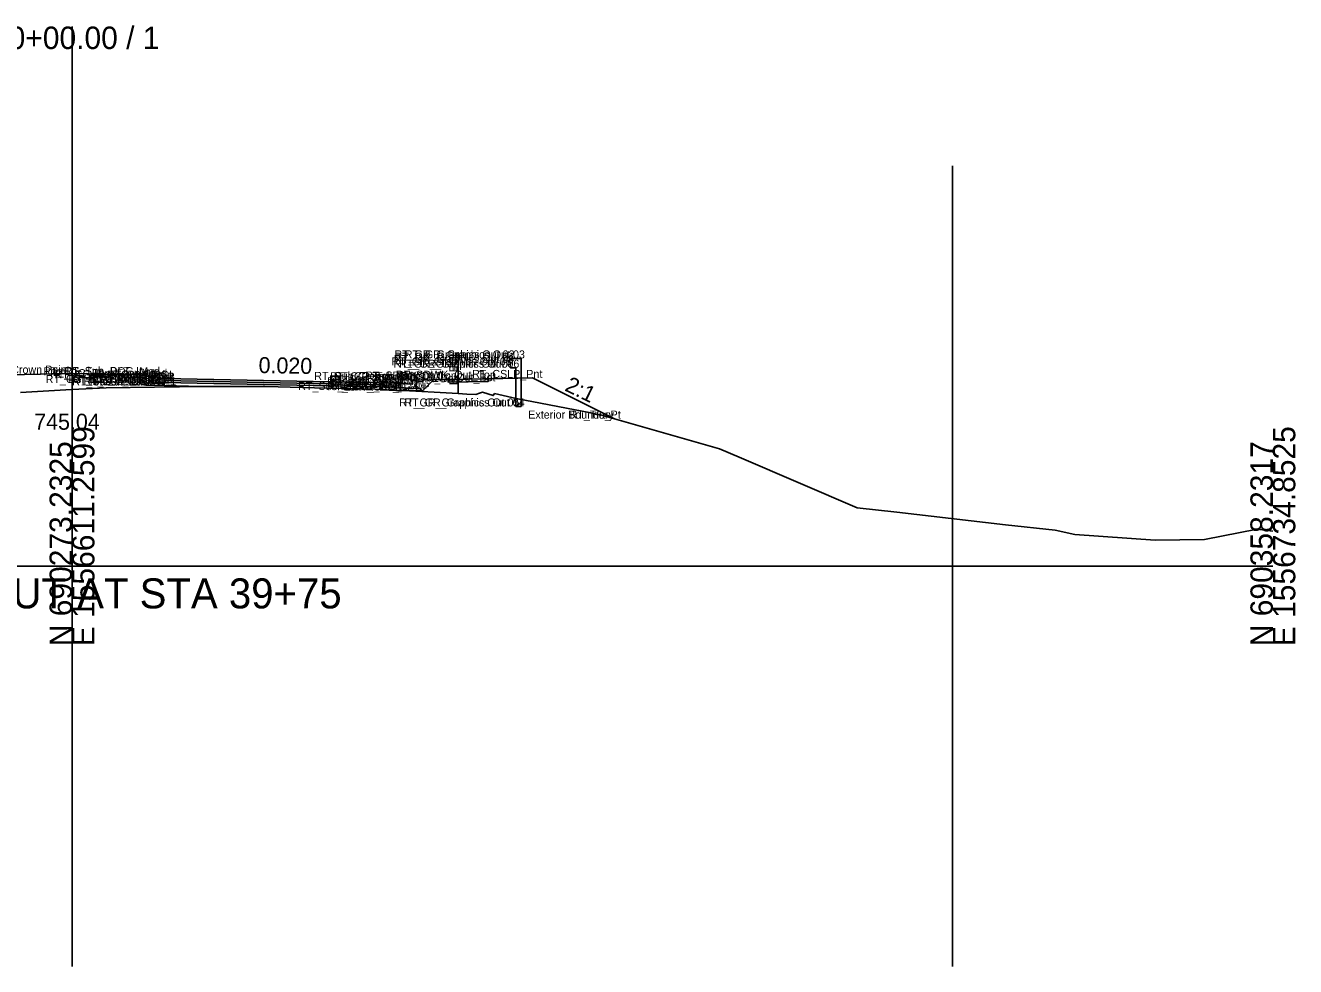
# Model space of a CAD drawing. Extents: x -26 to 6300, y -50 to 9577.
# Drawn here: x 144.2 to 302.8, y 6450 to 6567.5 of the extents above; entities that cross this region are included whole.
import ezdxf

# ---------------------------------------------------------------- set-up
doc = ezdxf.new("R2010")
doc.units = 0
for name, color, linetype in [('Default', 7, 'Continuous'), ('Exist CMT Pavement', 7, 'Continuous'), ('Exist Cross Section Cell', 7, 'Continuous'), ('Exist XS Center Line Elevation Label', 7, 'Continuous'), ('Exist XS Ground Line', 7, 'Continuous'), ('Prop CMT Conc Surface', 7, 'Continuous'), ('Prop CMT Concrete Structures', 7, 'Continuous'), ('Prop CMT Guardrail Graphics', 7, 'Continuous'), ('Prop CMT Pvmt Course 1', 7, 'Continuous'), ('Prop CMT Pvmt Course 1 CG', 7, 'Continuous'), ('Prop CMT Pvmt Course 2', 7, 'Continuous'), ('Prop CMT Pvmt Course 3', 7, 'Continuous'), ('Prop CMT Pvmt Surface', 7, 'Continuous'), ('Prop CMT Slope Grass', 7, 'Continuous'), ('Prop CMT Subgrade Earthwork', 7, 'Continuous'), ('Prop XS Earthwork Shape', 7, 'Continuous'), ('Prop XS Label Text', 7, 'Continuous'), ('Prop XS SE Text', 7, 'Continuous'), ('Prop XS Side Slope Text', 7, 'Continuous'), ('Prop XSC Text', 7, 'Continuous'), ('Scratch_Level_2', 7, 'Continuous'), ('Scratch_Level_9', 7, 'Continuous')]:
    doc.layers.add(name, color=color, linetype=linetype)

msp = doc.modelspace()

# ---------------------------------------------------------------- linework, layer by layer
at = {"layer": 'Exist CMT Pavement'}
msp.add_lwpolyline([(166.1, 6522.45), (168.19, 6522.46), (169.86, 6522.45), (171.3, 6522.45), (172.75, 6522.44), (174.06, 6522.42), (175.76, 6522.41), (178.77, 6522.32), (181.79, 6522.24), (184.82, 6522.17), (187.85, 6522.1), (188.5, 6522.07)], dxfattribs=at)
at = {"layer": 'Exist Cross Section Cell'}
for p, q in [((150, 6500), (150, 6567.38)), ((0, 6500), (150, 6500)), ((150, 6500), (300, 6500))]:
    msp.add_line(p, q, dxfattribs=at)
at = {"layer": 'Exist XS Ground Line'}
msp.add_lwpolyline([(143.57, 6521.71), (149.23, 6522.02), (150, 6522.06), (154.26, 6522.26), (160.3, 6522.36), (166.53, 6522.46), (169.86, 6522.45), (172.75, 6522.44), (174.06, 6522.42), (175.76, 6522.41), (181.79, 6522.24), (187.85, 6522.1), (190.04, 6521.99), (192.16, 6521.9), (195.23, 6521.74), (198.23, 6521.57), (199.3, 6521.5), (200.46, 6521.45), (200.9, 6521.6), (201.26, 6521.72), (202.62, 6521.31), (202.79, 6521.55), (205.5, 6520.96), (214.8, 6519.15), (215.56, 6518.95), (216.01, 6518.9), (230.88, 6514.66), (231.96, 6514.19), (233.64, 6513.5), (248.06, 6507.29), (253.04, 6506.73), (266.59, 6505.16), (272.79, 6504.52), (275.25, 6503.97), (285.31, 6503.24), (291.48, 6503.34), (298.02, 6504.64), (300, 6504.39)], dxfattribs=at)
at = {"layer": 'Prop CMT Conc Surface'}
for points in [[(161.5, 6523.42), (160.75, 6523.44), (160.75, 6523.6), (159.99, 6523.85)], [(190.5, 6522.84), (192.5, 6522.72)], [(192.5, 6522.72), (192.5, 6523.22), (193, 6523.22)], [(197, 6523.31), (202, 6523.41)]]:
    msp.add_lwpolyline(points, dxfattribs=at)
at = {"layer": 'Prop CMT Concrete Structures'}
for points in [[(161.5, 6523.42), (160.75, 6523.44), (160.75, 6523.6), (159.99, 6523.85)], [(159.99, 6523.85), (159.99, 6522.87)], [(159.99, 6522.87), (161.5, 6522.84)], [(161.5, 6522.84), (161.5, 6523.42)], [(190.5, 6522.84), (192.5, 6522.72), (192.5, 6523.22), (193, 6523.22)], [(193, 6523.22), (193, 6522.21), (190.5, 6522.26)], [(190.5, 6522.26), (190.5, 6522.84)], [(202, 6523.41), (197, 6523.31)], [(197, 6523.31), (197, 6522.98)], [(197, 6522.98), (202, 6523.08)], [(202, 6523.08), (202, 6523.41)]]:
    msp.add_lwpolyline(points, dxfattribs=at)
at = {"layer": 'Prop CMT Guardrail Graphics'}
for points in [[(206.1, 6525.95), (204.77, 6525.95), (204.5, 6525.66)], [(206.1, 6519.95), (206.1, 6525.95)], [(204.5, 6525.66), (204.77, 6525.37)], [(204.77, 6525.37), (204.5, 6525.08)], [(204.5, 6525.08), (204.77, 6524.79), (205.44, 6524.79)], [(205.44, 6524.79), (205.44, 6519.95)], [(205.44, 6519.95), (206.1, 6519.95)]]:
    msp.add_lwpolyline(points, dxfattribs=at)
at = {"layer": 'Prop CMT Pvmt Course 1'}
for points in [[(161.5, 6523.42), (190.5, 6522.84)], [(161.5, 6523.17), (161.5, 6523.42)], [(190.5, 6522.59), (161.5, 6523.17)], [(161.5, 6523.17), (161.5, 6523.17), (161.5, 6523.17)], [(188.5, 6522.88), (188.5, 6522.63)], [(190.5, 6522.84), (190.5, 6522.59)]]:
    msp.add_lwpolyline(points, dxfattribs=at)
at = {"layer": 'Prop CMT Pvmt Course 1 CG'}
for points in [[(161.5, 6522.84), (159.49, 6522.88), (159.2, 6522.59)], [(161.5, 6522.59), (161.5, 6522.84)], [(159.24, 6522.59), (161.5, 6522.55)], [(193.8, 6521.9), (188.5, 6522.01)], [(190.5, 6522.26), (193.5, 6522.2), (193.8, 6521.9)], [(190.5, 6522.01), (190.5, 6522.26)]]:
    msp.add_lwpolyline(points, dxfattribs=at)
at = {"layer": 'Prop CMT Pvmt Course 2'}
for points in [[(161.5, 6522.92), (161.5, 6523.17)], [(161.5, 6523.17), (190.5, 6522.59)], [(190.5, 6522.34), (161.5, 6522.92)], [(188.5, 6522.63), (188.5, 6522.38)], [(190.5, 6522.59), (190.5, 6522.34)]]:
    msp.add_lwpolyline(points, dxfattribs=at)
at = {"layer": 'Prop CMT Pvmt Course 3'}
for points in [[(161.5, 6522.92), (190.5, 6522.34)], [(161.5, 6522.55), (161.5, 6522.92)], [(166.1, 6522.45), (161.5, 6522.55)], [(188.5, 6522.38), (188.5, 6522.01)], [(190.5, 6522.34), (190.5, 6521.97)]]:
    msp.add_lwpolyline(points, dxfattribs=at)
at = {"layer": 'Prop CMT Pvmt Surface'}
msp.add_lwpolyline([(161.5, 6523.42), (190.5, 6522.84)], dxfattribs=at)
at = {"layer": 'Prop CMT Slope Grass'}
for points in [[(140.01, 6523.85), (150, 6524.05)], [(159.99, 6523.85), (150, 6524.05)], [(193, 6523.22), (207.5, 6523.51)], [(207.5, 6523.51), (217.67, 6518.43)]]:
    msp.add_lwpolyline(points, dxfattribs=at)
at = {"layer": 'Prop CMT Subgrade Earthwork'}
for p, q in [((193.8, 6521.9), (195.16, 6523.26)), ((188.5, 6522.01), (188.5, 6522.07))]:
    msp.add_line(p, q, dxfattribs=at)
for points in [[(157.9, 6523.89), (159.2, 6522.59)], [(159.2, 6522.59), (161.5, 6522.55)], [(161.5, 6522.55), (161.5, 6522.55)], [(161.5, 6522.55), (166.1, 6522.45)], [(188.5, 6522.01), (193.8, 6521.9)]]:
    msp.add_lwpolyline(points, dxfattribs=at)
at = {"layer": 'Prop XS Earthwork Shape'}
msp.add_lwpolyline([(143.57, 6521.71), (149.23, 6522.02), (150, 6522.06), (150, 6524.05), (142.1, 6523.89)], dxfattribs=at)
for points in [[(157.9, 6523.89), (159.2, 6522.59), (161.5, 6522.55), (166.1, 6522.45), (160.3, 6522.36), (154.26, 6522.26), (150, 6522.06), (150, 6524.05)], [(202.79, 6521.55), (205.5, 6520.96), (214.8, 6519.15), (215.56, 6518.95), (216.01, 6518.9), (217.67, 6518.43), (207.5, 6523.51), (202, 6523.41), (202, 6523.08), (197, 6522.98), (197, 6523.31), (195.17, 6523.27), (193.8, 6521.9), (190.7, 6521.96), (192.16, 6521.9), (195.23, 6521.74), (198.23, 6521.57), (199.3, 6521.5), (200.46, 6521.45), (200.9, 6521.6), (201.26, 6521.72), (202.62, 6521.31)], [(166.1, 6522.45), (166.53, 6522.46), (168.19, 6522.46)], [(188.5, 6522.01), (190.7, 6521.96), (190.04, 6521.99), (188.5, 6522.07)]]:
    msp.add_lwpolyline(points, close=True, dxfattribs=at)
at = {"layer": 'Prop XS Label Text'}
msp.add_line((198.23, 6526.57), (198.23, 6521.57), dxfattribs=at)
at = {"layer": 'Scratch_Level_2'}
msp.add_line((150, 6550), (150, 6450), dxfattribs=at)
at = {"layer": 'Scratch_Level_9'}
msp.add_line((260, 6550), (260, 6450), dxfattribs=at)

# ---------------------------------------------------------------- texts
at = {"layer": 'Default'}
for s, p in [('RT_GR_Graphics Out 08', (189.92, 6525.08)), ('RT_GR_Graphics Out 07', (190.17, 6524.79)), ('RT_GR_Graphics Out 09', (190.2, 6525.37)), ('RT_GR_Graphics Out 02', (190.26, 6525.95)), ('RT_GR_Graphics Out 01', (190.28, 6525.66)), ('RT_GR_Graphics Out 06', (190.86, 6524.79)), ('RT_GR_Graphics Out 03', (191.56, 6525.95)), ('MD_Crown Point', (139.58, 6524.05)), ('RT_CG_Top_BOC_Med', (146.43, 6523.85)), ('RT_CG_Top_Face_Med', (147.25, 6523.6)), ('RT_CG_Top_Gut_Med', (147.8, 6523.44)), ('RT_Sub_DLT_In', (149.07, 6523.89)), ('RT_PV1_PGL', (154.38, 6523.42)), ('RT_Sub_Trench_Out_DLT', (180.26, 6523.26)), ('RT_CG_Top_Face', (182.22, 6523.22)), ('RT_CG_Top_BOC', (182.69, 6523.22)), ('RT_SDWK_In_Top', (186.62, 6523.31)), ('RT_SDWK_Out_Top', (190.46, 6523.41)), ('RT_CSLP_Pnt', (199.98, 6523.51)), ('RT_CG_Bot_BOC_Med', (146.71, 6522.87)), ('RT_CG1_Shelf_In', (149.57, 6522.88)), ('RT_CG_Bot_IE_Med', (149.98, 6522.84)), ('RT_Sub_IEOT_CG_1', (150.01, 6522.59)), ('RT_Sub_IEOP', (151.42, 6522.63)), ('RT_PV2_OEEOP', (152.17, 6523.17)), ('RT_PV3_OEEOP', (152.17, 6522.92)), ('RT_Sub_OEEOP', (152.21, 6522.55)), ('RT_PV2_IEEOP', (152.93, 6523.17)), ('RT_Sub_IEEOP', (152.97, 6522.55)), ('RT_PV2_PGL', (154.15, 6523.17)), ('RT_Sub_PGL', (154.19, 6522.55)), ('RT_Sub_OEOT_CG_1', (178.25, 6522.01)), ('RT_PV2_OEOT', (181.87, 6522.59)), ('RT_PV3_OEOT', (181.87, 6522.34)), ('RT_Sub_OEOT', (181.92, 6521.97)), ('RT_PV1_OEOT', (182.11, 6522.84)), ('RT_CG_Bot_IE', (182.22, 6522.26)), ('RT_CG1_Shelf_Out', (182.36, 6522.2)), ('RT_CG_Top_Gut', (182.75, 6522.72)), ('RT_CG_Bot_BOC', (182.97, 6522.21)), ('RT_Sub_OEOP', (185.17, 6521.94)), ('RT_SDWK_In_Bot', (186.87, 6522.98)), ('RT_SDWK_Out_Bot', (190.71, 6523.08)), ('RT_GR_Graphics Out 05', (190.88, 6519.95)), ('RT_GR_Graphics Out 04', (191.52, 6519.95)), ('Exterior Boundary', (206.99, 6518.43)), ('RT_Tie_Pt', (212.15, 6518.43))]:
    msp.add_text(s, height=1, dxfattribs=at).set_placement(p)
at = {"layer": 'Exist Cross Section Cell'}
msp.add_text('40+00.00 / 1', height=2.8, dxfattribs=at).set_placement((140, 6564.58))
for s, p in [('E 1556611.2599', (152.8, 6490)), ('E 1556734.8525', (302.8, 6490)), ('N 690273.2325', (150, 6490)), ('N 690358.2317', (300, 6490))]:
    msp.add_text(s, height=2.8, rotation=90, dxfattribs=at).set_placement(p)
at = {"layer": 'Exist XS Center Line Elevation Label'}
msp.add_text('745.04', height=2, dxfattribs=at).set_placement((145.28, 6517.04))
at = {"layer": 'Prop XS Label Text'}
msp.add_text('E. EOP', height=1, rotation=90, dxfattribs=at).set_placement((198.13, 6522.59))
at = {"layer": 'Prop XS SE Text'}
msp.add_text('0.020', height=2, rotation=358.8542, dxfattribs=at).set_placement((173.29, 6524.13))
at = {"layer": 'Prop XS Side Slope Text'}
msp.add_text('2:1', height=2, rotation=333.9281, dxfattribs=at).set_placement((211.43, 6521.98))
at = {"layer": 'Prop XSC Text'}
msp.add_text('BEGIN UNDERCUT AT STA 39+75', height=3.75, dxfattribs=at).set_placement((104.12, 6494.73))

doc.saveas('drawing.dxf')
